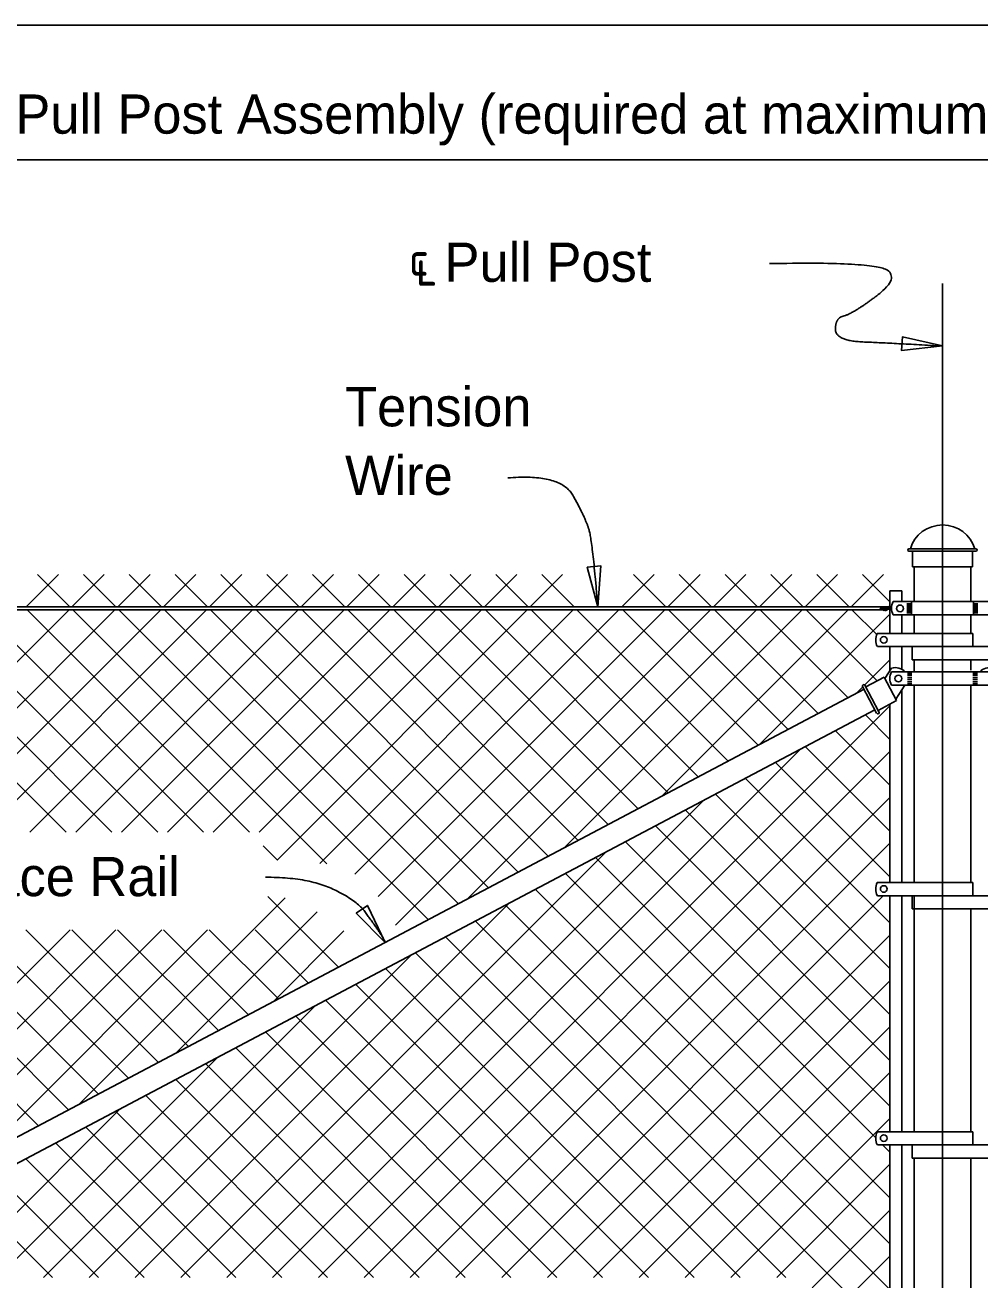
# Model space of a CAD drawing. Extents: x 0 to 72.1, y -7 to 30.
# Drawn here: x 7.5 to 12.41, y 21.56 to 28.01 of the extents above; entities that cross this region are included whole.
import ezdxf

# ---------------------------------------------------------------- set-up
doc = ezdxf.new("R2010")
doc.units = 0
for name, color, linetype in [('ActivePts-ConstElements', 7, 'Continuous'), ('AdhocPoint_dp', 7, 'Continuous'), ('Border', 7, 'Continuous'), ('PlotBorder_dp', 7, 'Continuous'), ('SheetBorder_dp', 7, 'Continuous'), ('TextStructures', 7, 'Continuous')]:
    doc.layers.add(name, color=color, linetype=linetype)

msp = doc.modelspace()

# ---------------------------------------------------------------- linework, layer by layer
at = {"layer": 'ActivePts-ConstElements'}
msp.add_lwpolyline([(0.016, 2.0538), (41.2266, 2.0538), (41.2266, 28.0138), (0.016, 28.0138)], close=True, dxfattribs=at)
at = {"layer": 'AdhocPoint_dp'}
for p, q in [((7.676, 25.1899), (7.5094, 25.0233)), ((7.7352, 25.0233), (7.5686, 25.1899)), ((7.9117, 25.1899), (7.7451, 25.0233)), ((7.9709, 25.0233), (7.8043, 25.1899)), ((8.1474, 25.1899), (7.9808, 25.0233)), ((8.2066, 25.0233), (8.04, 25.1899)), ((8.3831, 25.1899), (8.2165, 25.0233)), ((8.4423, 25.0233), (8.2757, 25.1899)), ((8.6188, 25.1899), (8.4522, 25.0233)), ((8.678, 25.0233), (8.5114, 25.1899)), ((8.8545, 25.1899), (8.6879, 25.0233)), ((8.9138, 25.0233), (8.7471, 25.1899)), ((9.0902, 25.1899), (8.9236, 25.0233)), ((9.1495, 25.0233), (8.9828, 25.1899)), ((9.3259, 25.1899), (9.1593, 25.0233)), ((9.3852, 25.0233), (9.2185, 25.1899)), ((9.5616, 25.1899), (9.395, 25.0233)), ((9.6209, 25.0233), (9.4542, 25.1899)), ((9.7973, 25.1899), (9.6307, 25.0233)), ((9.8566, 25.0233), (9.6899, 25.1899)), ((10.033, 25.1899), (9.8664, 25.0233)), ((10.0923, 25.0233), (9.9256, 25.1899)), ((10.2687, 25.1899), (10.1021, 25.0233)), ((10.328, 25.0233), (10.1613, 25.1899)), ((10.7401, 25.1899), (10.5735, 25.0233)), ((10.7994, 25.0233), (10.6327, 25.1899)), ((10.9758, 25.1899), (10.8092, 25.0233)), ((11.0351, 25.0233), (10.8684, 25.1899)), ((11.2116, 25.1899), (11.0449, 25.0233)), ((11.2708, 25.0233), (11.1041, 25.1899)), ((11.4473, 25.1899), (11.2806, 25.0233)), ((11.5065, 25.0233), (11.3398, 25.1899)), ((11.683, 25.1899), (11.5163, 25.0233)), ((11.7422, 25.0233), (11.5755, 25.1899)), ((11.9187, 25.1899), (11.752, 25.0233)), ((11.9513, 25.0498), (11.8112, 25.1899)), ((7.7303, 25.0085), (4.7648, 22.043)), ((7.5736, 22.3564), (4.9216, 25.0085)), ((7.966, 25.0085), (5.0005, 22.043)), ((7.7279, 22.4379), (5.1573, 25.0085)), ((7.7151, 23.8649), (6.5715, 25.0085)), ((7.9508, 23.8649), (6.8072, 25.0085)), ((8.1865, 23.8649), (7.0429, 25.0085)), ((8.2017, 25.0085), (7.057, 23.8638)), ((8.4222, 23.8649), (7.2786, 25.0085)), ((8.4374, 25.0085), (7.2938, 23.8649)), ((8.6579, 23.8649), (7.5143, 25.0085)), ((8.6731, 25.0085), (7.5295, 23.8649)), ((9.0561, 23.7024), (7.75, 25.0085)), ((8.9088, 25.0085), (7.7652, 23.8649)), ((9.5784, 23.4158), (7.9857, 25.0085)), ((9.1445, 25.0085), (8.0009, 23.8649)), ((9.7326, 23.4973), (8.2214, 25.0085)), ((9.3802, 25.0085), (8.2366, 23.8649)), ((9.8868, 23.5788), (8.4571, 25.0085)), ((9.6159, 25.0085), (8.4723, 23.8649)), ((10.041, 23.6603), (8.6928, 25.0085)), ((9.8516, 25.0085), (8.708, 23.8649)), ((10.0873, 25.0085), (8.8001, 23.7213)), ((10.1952, 23.7418), (8.9285, 25.0085)), ((10.323, 25.0085), (9.0196, 23.7051)), ((10.3494, 23.8233), (9.1642, 25.0085)), ((10.5587, 25.0085), (9.1993, 23.6491)), ((10.7944, 25.0085), (9.3209, 23.535)), ((10.5036, 23.9048), (9.3999, 25.0085)), ((11.0301, 25.0085), (9.41, 23.3884)), ((10.6578, 23.9863), (9.6356, 25.0085)), ((11.2658, 25.0085), (9.7794, 23.5221)), ((10.812, 24.0678), (9.8713, 25.0085)), ((10.9663, 24.1493), (10.107, 25.0085)), ((11.5015, 25.0085), (10.2792, 23.7862)), ((11.1205, 24.2308), (10.3427, 25.0085)), ((11.2747, 24.3123), (10.5784, 25.0085)), ((11.7372, 25.0085), (10.7791, 24.0504)), ((11.4289, 24.3938), (10.8141, 25.0085)), ((11.5831, 24.4752), (11.0498, 25.0085)), ((11.9513, 24.9869), (11.2789, 24.3145)), ((11.7373, 24.5567), (11.2855, 25.0085)), ((11.8865, 24.6433), (11.5212, 25.0085)), ((11.8843, 24.8811), (11.7569, 25.0085)), ((11.9513, 24.7512), (11.8225, 24.6224)), ((11.8126, 24.6125), (11.7788, 24.5787)), ((11.9513, 24.5155), (9.013, 21.5771)), ((11.9513, 24.3427), (11.8261, 24.468)), ((11.9513, 24.107), (11.6719, 24.3865)), ((11.4911, 24.291), (8.7773, 21.5771)), ((11.9513, 24.2798), (9.2487, 21.5771)), ((11.9513, 23.8713), (11.5176, 24.305)), ((11.9513, 23.6356), (11.3634, 24.2235)), ((11.9513, 23.3999), (11.2092, 24.142)), ((11.9513, 23.1642), (11.055, 24.0605)), ((10.9912, 24.0268), (8.5416, 21.5771)), ((11.9513, 24.0441), (9.4844, 21.5771)), ((11.9513, 22.9285), (10.9008, 23.979)), ((11.9513, 22.6928), (10.7466, 23.8975)), ((11.9513, 23.8084), (9.7201, 21.5771)), ((11.9513, 22.4571), (10.5924, 23.816)), ((10.4914, 23.7627), (8.3059, 21.5771)), ((8.8016, 23.7212), (8.7279, 23.7949)), ((11.8788, 22.2939), (10.4382, 23.7346)), ((11.9513, 21.9857), (10.284, 23.6531)), ((11.9513, 21.75), (10.1297, 23.5716)), ((8.8424, 23.5279), (7.78, 22.4655)), ((9.9916, 23.4986), (8.0702, 21.5771)), ((9.1157, 23.1714), (8.7526, 23.5345)), ((11.9173, 23.5386), (9.9558, 21.5771)), ((11.9513, 21.5143), (9.9755, 23.4901)), ((9.0063, 23.4561), (8.2798, 22.7296)), ((7.736, 23.3643), (5.7806, 21.4089)), ((7.9717, 23.3643), (6.2804, 21.673)), ((8.2074, 23.3643), (6.7803, 21.9372)), ((7.8821, 22.5194), (7.0372, 23.3643)), ((8.0363, 22.6009), (7.2729, 23.3643)), ((8.4431, 23.3643), (7.2801, 22.2013)), ((8.1905, 22.6824), (7.5086, 23.3643)), ((8.3447, 22.7639), (7.7443, 23.3643)), ((8.4989, 22.8454), (7.98, 23.3643)), ((8.6531, 22.9269), (8.2157, 23.3643)), ((8.8073, 23.0084), (8.4514, 23.3643)), ((8.9615, 23.0899), (8.6871, 23.3643)), ((9.1437, 23.3578), (8.7797, 22.9938)), ((11.9513, 21.2786), (9.8213, 23.4086)), ((11.4171, 21.5771), (9.6671, 23.3271)), ((11.9513, 23.337), (10.1915, 21.5771)), ((9.4917, 23.2344), (7.8345, 21.5771)), ((11.1814, 21.5771), (9.5129, 23.2456)), ((10.9457, 21.5771), (9.3587, 23.1641)), ((11.9513, 23.1013), (10.4272, 21.5771)), ((10.71, 21.5771), (9.2045, 23.0826)), ((8.9919, 22.9703), (7.5988, 21.5771)), ((10.4743, 21.5771), (9.0503, 23.0011)), ((10.2386, 21.5771), (8.8961, 22.9196)), ((10.0029, 21.5771), (8.7418, 22.8381)), ((11.9513, 22.8656), (10.6629, 21.5771)), ((8.4921, 22.7062), (5.1573, 19.3714)), ((9.7671, 21.5771), (8.5876, 22.7567)), ((9.5314, 21.5771), (8.4334, 22.6752)), ((9.2957, 21.5771), (8.2792, 22.5937)), ((11.9513, 22.6299), (10.8986, 21.5771)), ((9.06, 21.5771), (8.125, 22.5122)), ((7.9922, 22.442), (4.9216, 19.3714)), ((8.8243, 21.5771), (7.9708, 22.4307)), ((11.9513, 22.3942), (11.1343, 21.5771)), ((8.5886, 21.5771), (7.8166, 22.3492)), ((8.3529, 21.5771), (7.6624, 22.2677)), ((11.9513, 22.2214), (11.9146, 22.2581)), ((8.1172, 21.5771), (7.5082, 22.1862)), ((11.9513, 22.1585), (11.37, 21.5771)), ((7.8815, 21.5771), (7.354, 22.1047)), ((7.6458, 21.5771), (7.1997, 22.0232)), ((11.9513, 21.9228), (11.5523, 21.5238)), ((11.9513, 21.6871), (11.5523, 21.288))]:
    msp.add_line(p, q, dxfattribs=at)
at = {"layer": 'Border'}
msp.add_line((2.2222, 27.321), (22.2222, 27.321), dxfattribs=at)
for points in [[(12.2223, 26.3645), (12.0163, 26.4111), (12.0124, 26.3406)], [(10.4498, 25.0233), (10.4655, 25.234), (10.3952, 25.2274)], [(9.3565, 23.2986), (9.2652, 23.4891), (9.2076, 23.4484)]]:
    msp.add_lwpolyline(points, close=True, dxfattribs=at)
for points in [[(11.3327, 26.7882), (11.8785, 26.798), (12.0009, 26.7091), (11.7567, 26.5278), (11.6718, 26.5094), (11.6718, 26.3916), (11.9499, 26.3793), (12.2222, 26.3644)], [(9.9878, 25.6864), (10.2595, 25.7087), (10.3858, 25.4816), (10.4225, 25.36), (10.4497, 25.0233)], [(8.7405, 23.634), (8.9548, 23.634), (9.2071, 23.5174), (9.2882, 23.4075), (9.3537, 23.3122), (9.3565, 23.2986)]]:
    msp.add_open_spline(points, degree=2, dxfattribs=at)
at = {"layer": 'PlotBorder_dp'}
for p, q in [((12.05, 25.3219), (12.3946, 25.3219)), ((12.3946, 25.3097), (12.05, 25.3097)), ((12.0682, 25.2299), (12.0682, 25.3097)), ((12.3763, 25.2299), (12.3763, 25.3097)), ((12.3763, 25.2299), (12.0682, 25.2299)), ((12.0764, 25.0504), (12.0764, 25.2299)), ((12.3681, 25.0504), (12.3681, 25.2299)), ((11.9513, 25.0264), (11.9513, 25.1066)), ((12.0138, 25.1066), (11.9513, 25.1066)), ((12.0138, 25.0504), (12.0138, 25.1066)), ((11.961, 25.0279), (11.9317, 25.0233)), ((12.3781, 25.0504), (11.9683, 25.0504)), ((12.0397, 25.0396), (12.0627, 25.0396)), ((12.0397, 25.0341), (12.0627, 25.0341)), ((12.0397, 25.026), (12.0627, 25.026)), ((12.0627, 24.9827), (12.0627, 25.0504)), ((12.0665, 25.0504), (12.4762, 25.0504)), ((12.4047, 25.0396), (12.3817, 25.0396)), ((12.4047, 25.0341), (12.3817, 25.0341)), ((12.4047, 25.026), (12.3817, 25.026)), ((12.3818, 24.9827), (12.3818, 25.0504)), ((11.9403, 25.0085), (2.5165, 25.0085)), ((11.939, 25.0233), (2.5432, 25.0233)), ((11.9604, 25.0075), (11.9267, 25.0131)), ((11.96, 25.0123), (11.9302, 25.0172)), ((11.9603, 25.0229), (11.9342, 25.0189)), ((11.9513, 25.0215), (11.9513, 25.0136)), ((11.9513, 25.009), (11.9513, 24.8868)), ((12.3781, 24.9827), (11.9687, 24.9827)), ((12.0138, 24.9826), (12.0138, 24.8868)), ((12.0397, 25.0205), (12.0627, 25.0205)), ((12.0397, 25.0125), (12.0627, 25.0125)), ((12.0397, 25.0069), (12.0627, 25.0069)), ((12.0397, 24.9989), (12.0627, 24.9989)), ((12.0397, 24.9934), (12.0627, 24.9934)), ((12.0665, 24.9827), (12.4759, 24.9827)), ((12.0764, 24.8868), (12.0764, 24.9826)), ((12.3681, 24.8868), (12.3681, 24.9826)), ((12.4047, 25.0205), (12.3817, 25.0205)), ((12.4047, 25.0125), (12.3817, 25.0125)), ((12.4047, 25.0069), (12.3817, 25.0069)), ((12.4047, 24.9989), (12.3817, 24.9989)), ((12.4047, 24.9934), (12.3817, 24.9934)), ((12.3781, 24.8868), (11.887, 24.8868)), ((12.3781, 24.8868), (12.3781, 24.8192)), ((12.3781, 24.8192), (11.8877, 24.8192)), ((11.9513, 24.6948), (11.9513, 24.8192)), ((12.0138, 24.7025), (12.0138, 24.8192)), ((12.0665, 24.8192), (12.0665, 24.7516)), ((12.0665, 24.8192), (12.5576, 24.8192)), ((11.9256, 24.6556), (11.9604, 24.7087)), ((12.0665, 24.7516), (12.5568, 24.7516)), ((12.0764, 24.6896), (12.0764, 24.7516)), ((12.3681, 24.6984), (12.3681, 24.7516)), ((11.9222, 24.6621), (11.8279, 24.6123)), ((11.9222, 24.6621), (11.9859, 24.5416)), ((11.9599, 24.6896), (12.4847, 24.6896)), ((12.0422, 24.6818), (12.0656, 24.6818)), ((12.0422, 24.6722), (12.0656, 24.6722)), ((12.0422, 24.6614), (12.0656, 24.6614)), ((12.0422, 24.6496), (12.0656, 24.6496)), ((12.0422, 24.6378), (12.0656, 24.6378)), ((12.4023, 24.6818), (12.3788, 24.6818)), ((12.4023, 24.6722), (12.3788, 24.6722)), ((12.4023, 24.6614), (12.3788, 24.6614)), ((12.4023, 24.6496), (12.3788, 24.6496)), ((12.4023, 24.6378), (12.3788, 24.6378)), ((2.5696, 19.712), (11.8192, 24.6)), ((11.8114, 24.6147), (11.8839, 24.4776)), ((11.8233, 24.6209), (11.8958, 24.4838)), ((11.9599, 24.6218), (12.4847, 24.6218)), ((11.9817, 24.5496), (12.0286, 24.6213)), ((12.0138, 23.6062), (12.0138, 24.5988)), ((12.0422, 24.628), (12.0656, 24.628)), ((12.0764, 23.6062), (12.0764, 24.6218)), ((12.3681, 23.6062), (12.3681, 24.6218)), ((12.4023, 24.628), (12.3788, 24.628)), ((11.8916, 24.4917), (11.9859, 24.5416)), ((11.9513, 23.6062), (11.9513, 24.5233)), ((2.6255, 19.606), (11.8752, 24.494)), ((12.3781, 23.6062), (11.887, 23.6062)), ((12.3781, 23.6062), (12.3781, 23.5386)), ((12.3781, 23.5386), (11.8877, 23.5386)), ((11.9513, 22.3257), (11.9513, 23.5386)), ((12.0138, 22.3257), (12.0138, 23.5386)), ((12.0665, 23.5386), (12.0665, 23.471)), ((12.0665, 23.5386), (12.5576, 23.5386)), ((12.0764, 22.3257), (12.0764, 23.5386)), ((12.0665, 23.471), (12.5568, 23.471)), ((12.3681, 22.3257), (12.3681, 23.471)), ((12.3781, 22.3257), (11.887, 22.3257)), ((12.3781, 22.3257), (12.3781, 22.2581)), ((12.3781, 22.2581), (11.8877, 22.2581)), ((11.9513, 21.0453), (11.9513, 22.2581)), ((12.0138, 21.0453), (12.0138, 22.2581)), ((12.0665, 22.2581), (12.0665, 22.1905)), ((12.0665, 22.2581), (12.5576, 22.2581)), ((12.0665, 22.1905), (12.5568, 22.1905)), ((12.0764, 21.0453), (12.0764, 22.1905)), ((12.3681, 21.0453), (12.3681, 22.1905))]:
    msp.add_line(p, q, dxfattribs=at)
for centre, radius, start, end in [((12.0501, 25.3156), 0.00613, 91.1647, 268.8353), ((12.3944, 25.3156), 0.00613, 271.1647, 88.8353), ((11.8175, 24.6177), 0.00673, 27.85098, 207.85098), ((11.89, 24.4805), 0.00673, 207.85098, 27.85098)]:
    msp.add_arc(centre, radius, start, end, dxfattribs=at)
for centre, major_axis, ratio, start_param, end_param in [((12.2229, 25.2808), (0.1711, 0), 0.957868, 0.252602, 2.888574), ((11.9208, 25.0155), (0.00872, 0), 0.957868, 1.29026, 2.959852), ((11.9274, 25.015), (0.00872, 0), 0.957868, 1.29026, 4.182385), ((12.0375, 25.0168), (-0.0776, 0), 0.957868, 5.81433, 6.762456), ((11.9161, 25.01), (0.0142, 0), 0.957868, 1.486836, 3.141593), ((11.9241, 24.995), (-0.0274, 0), 0.957868, 5.133531, 5.654664), ((11.9213, 25.0146), (-0.00944, 0), 0.957868, 6.009018, 8.249874), ((11.9208, 25.0155), (0.00503, 0), 0.92697, 1.570796, 4.502291), ((11.9331, 25.0142), (-0.0115, -0.0041), 0.737732, 4.35367, 7.47816), ((11.9318, 25.0126), (-0.00527, 0), 0.957868, 5.22362, 7.507542), ((11.9296, 25.0117), (-0.00301, 0), 0.957868, 6.141288, 6.278592), ((11.935, 25.0093), (-0.00982, 0), 0.957868, 4.777514, 5.62749), ((11.9296, 25.0117), (-0.00301, 0), 0.957868, 1.11255, 2.999696), ((11.929, 25.0139), (0.00453, 0), 0.957868, 0.731188, 1.133458), ((11.9291, 25.0135), (0.0095, 0), 0.957868, 5.011765, 6.030719), ((11.9291, 25.0135), (0.0095, 0), 0.957868, 0.230606, 0.609214), ((11.9564, 24.8536), (-0.0776, 0), 0.957868, 5.821213, 6.765127), ((11.977, 24.6404), (0.0647, 0.0342), 0.957868, 0.271397, 1.331255), ((12.4674, 24.6404), (-0.0647, 0.0342), 0.957868, 4.95193, 6.011789), ((12.029, 24.6554), (-0.0776, 0), 0.957868, 5.810211, 6.75616), ((11.9564, 23.5731), (-0.0776, 0), 0.957868, 5.821408, 6.765324), ((11.9564, 22.2926), (-0.0776, 0), 0.957868, 5.821604, 6.765522)]:
    msp.add_ellipse(centre, major_axis=major_axis, ratio=ratio, start_param=start_param, end_param=end_param, dxfattribs=at)
for centre, major_axis in [((12.0042, 25.0159), (0.0178, 0)), ((11.9205, 24.854), (0.0177, 0)), ((11.9956, 24.655), (0.0178, 0)), ((11.9205, 23.5735), (0.0177, 0)), ((11.9205, 22.293), (0.0177, 0))]:
    msp.add_ellipse(centre, major_axis=major_axis, ratio=0.957868, dxfattribs=at)
at = {"layer": 'SheetBorder_dp'}
msp.add_line((12.2222, 26.6864), (12.2222, 16.7178), dxfattribs=at)

# ---------------------------------------------------------------- texts
at = {"layer": 'Border'}
for s, p in [('Tension ', (9.1498, 25.9514)), ('Wire ', (9.1498, 25.5994))]:
    msp.add_text(s, height=0.2016, dxfattribs=at).set_placement(p)
at = {"layer": 'TextStructures'}
for s, p in [('Pull Post Assembly (required at maximum intervals of 500\'-0")', (7.4543, 27.4558)), ('℄ Pull Post', (9.4772, 26.6943)), ('Brace Rail', (7.0562, 23.5367))]:
    msp.add_text(s, height=0.2016, dxfattribs=at).set_placement(p)

doc.saveas('drawing.dxf')
